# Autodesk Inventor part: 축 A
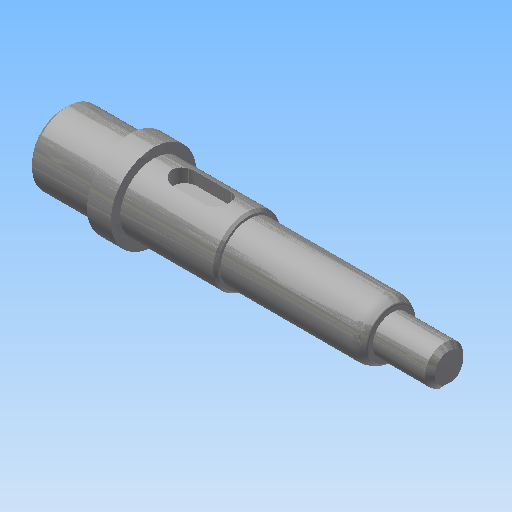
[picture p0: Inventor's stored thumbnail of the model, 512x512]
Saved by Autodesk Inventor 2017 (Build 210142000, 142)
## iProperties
Created: 2020-04
Part Number: 축 A
Material: 강철, 연강
Document SubType Name: Modeling
Designer: mduedu
Density: 1 g/cm^3
Appearance: 강철
Author: mduedu
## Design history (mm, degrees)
sketch "스케치1"
  geometry: L1 (0, 0)-(14, 0); L2 (14, 0)-(14, 7.5); L3 (14, 7.5)-(0, 7.5); L4 (0, 7.5)-(0, 0); L5 (14, 0)-(19, 0); L6 (19, 0)-(19, 9); L7 (19, 9)-(14, 9); L8 (14, 9)-(14, 0); L9 (19, 0)-(39, 0); L10 (39, 0)-(39, 7); L11 (39, 7)-(19, 7); L12 (19, 7)-(19, 0); L13 (39, 0)-(69, 0); L14 (69, 0)-(69, 6); L15 (69, 6)-(39, 6); L16 (39, 6)-(39, 0); L17 (69, 0)-(81, 0); L18 (81, 0)-(81, 4); L19 (81, 4)-(69, 4); L20 (69, 4)-(69, 0)
  constraints: 40 end point, 10 parallel, 5 horizontal, 5 perpendicular
  dimensions: "d0" = 81 distance between parallel lines of L18 L4; "d2" = 14 distance of L2.end L3.end; "d3" = 5 distance of L6.end L7.end; "d4" = 12 distance of L18.end L19.end; "d5" = 8 diameter of L19 L17; "d6" = 12 diameter of L15 L13; "d7" = 14 diameter of L11 L9; "d8" = 15 diameter of L3 L1; "d9" = 18 diameter of L7 L5; "d10" = 42 distance between parallel lines of L10 L18
revolve "회전1" sketch "스케치1" stored, may be unused: angle "d11" = 90 deg
sketch "스케치2"
  geometry: L1 (0, -7.5)-(0, 7.5) reference; L2 (0, 7.5)-(14, 7.5) reference; L3 (14, 7.5)-(14, 9) reference; L4 (14, 9)-(19, 9) reference; L5 (19, 9)-(19, 7) reference; L6 (19, 7)-(39, 7) reference; L7 (39, 7)-(39, 6) reference; L8 (39, 6)-(69, 6) reference; L9 (69, 6)-(69, 4) reference; L10 (69, 4)-(81, 4) reference; L11 (81, 4)-(81, -4) reference; L12 (81, -4)-(69, -4) reference; L13 (69, -4)-(69, -6) reference; L14 (69, -6)-(39, -6) reference; L15 (39, -6)-(39, -7) reference; L16 (39, -7)-(19, -7) reference; L17 (19, -7)-(19, -9) reference; L18 (19, -9)-(14, -9) reference; L19 (14, -9)-(14, -7.5) reference; L20 (14, -7.5)-(0, -7.5) reference; L21 (81, -4)-(73, -4); L22 (73, -4)-(73, -2.8); L23 (73, -2.8)-(81, -2.8); L24 (81, -2.8)-(81, -4); 1 further point
  constraints: 8 end point, 2 parallel, 1 horizontal, 1 perpendicular
  dimensions: "d12" = 8 distance of L22.end L23.end; "d13" = 1.2 distance of L21.end L22.end
extrude "돌출1" cut sketch "스케치2" stored distance "d14" = 2; taper "d15" = 0 deg
fillet "모깎기1" dims "d16" = 1
sketch "스케치3"
  geometry: L1 (0, -7.5)-(0, 7.5) reference; L2 (0, 7.5)-(14, 7.5) reference; L3 (14, 7.5)-(14, 9) reference; L4 (14, 9)-(19, 9) reference; L5 (19, 9)-(19, 7) reference; L6 (19, 7)-(39, 7) reference; L7 (39, 7)-(39, 6) reference; L8 (39, 6)-(69, 6) reference; L9 (69, 6)-(69, 4) reference; L10 (69, 4)-(81, 4) reference; L11 (81, 4)-(81, -2.8) reference; L12 (81, -2.8)-(73, -2.8) reference; L13 (73, -2.8)-(73, -4) reference; L14 (73, -4)-(69, -4) reference; L15 (69, -4)-(69, -6) reference; L16 (69, -6)-(39, -6) reference; L17 (39, -6)-(39, -7) reference; L18 (39, -7)-(19, -7) reference; L19 (19, -7)-(19, -9) reference; L20 (19, -9)-(14, -9) reference; L21 (14, -9)-(14, -7.5) reference; L22 (14, -7.5)-(0, -7.5) reference; L23 (23, 7)-(35, 7); L24 (35, 7)-(35, 4); L25 (35, 4)-(23, 4); L26 (23, 4)-(23, 7); 1 further point
  constraints: 8 end point, 2 parallel, 1 horizontal, 1 perpendicular, 1 point on line
  dimensions: "d17" = 12 distance of L24.end L25.end; "d18" = 3 distance of L23.end L24.end; "d19" = 4 distance from line of L26 L4.end
extrude "돌출2" cut sketch "스케치3" stored distance "d20" = 5; taper "d21" = 0 deg
fillet "모깎기2" dims "d22" = 2.5
chamfer "모따기1" distance "d23" = 1; stored, may be unused: second distance "d24" = 2, angle "d25" = 45 deg
chamfer "모따기2" distance "d26" = 0.5; stored, may be unused: second distance "d27" = 2, angle "d28" = 45 deg
fillet "모깎기3" dims "d29" = 0.3
chamfer "모따기3" distance "d30" = 1.56; stored, may be unused: second distance "d31" = 2, angle "d32" = 30 deg
fillet "모깎기4" dims "d33" = 4, "d34" = 0.5
node "솔리드1"
node "절단 모서리 투영1"
node "절단 모서리 투영2"
